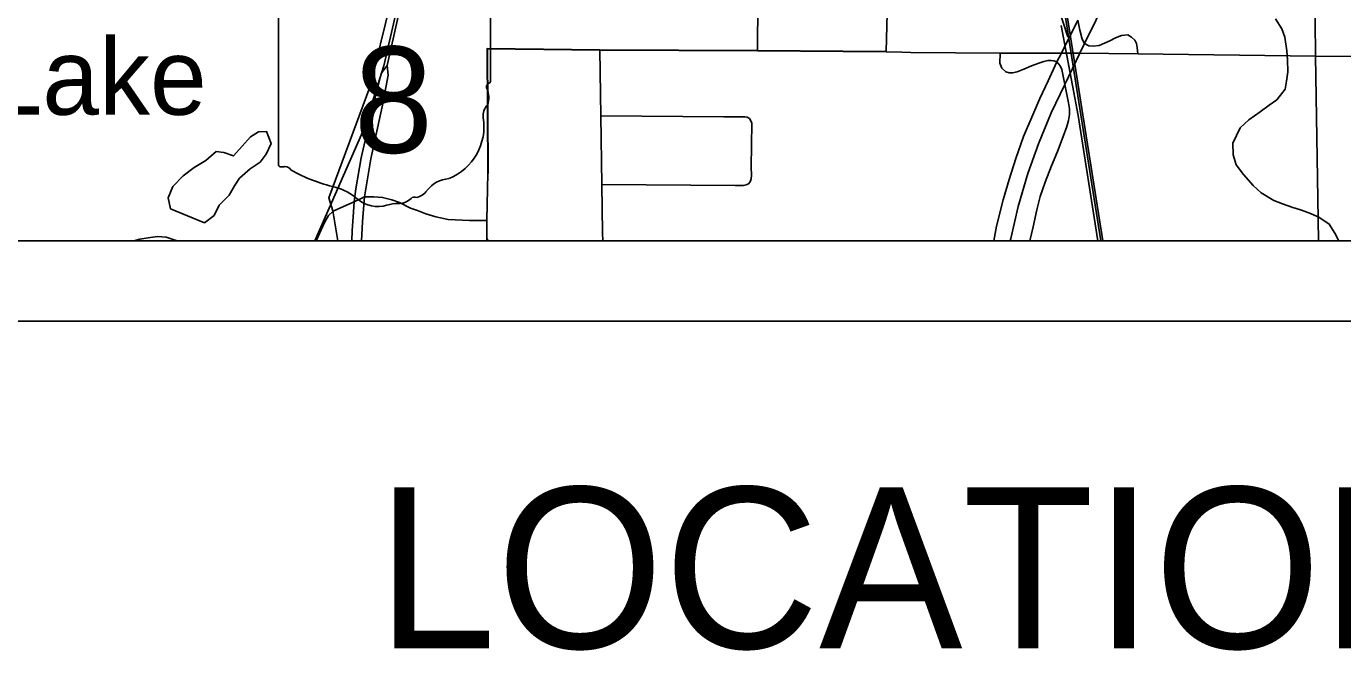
# Model space of a CAD drawing. Extents: x 0 to 34, y 0 to 22.
# Drawn here: x 3.992 to 5.628, y 13.591 to 14.366 of the extents above; entities that cross this region are included whole.
import ezdxf

# ---------------------------------------------------------------- set-up
doc = ezdxf.new("R2010")
doc.units = 0
for name, color, linetype in [('GM_X_City_Street', 7, 'Continuous'), ('GM_X_County_Road', 7, 'Continuous'), ('GM_X_County_Text', 7, 'Continuous'), ('GM_X_Interstate_Route', 7, 'Continuous'), ('GM_X_Minor_Lake', 7, 'Continuous'), ('GM_X_Minor_Lake_Text', 7, 'Continuous'), ('GM_X_Minor_River', 7, 'Continuous'), ('GM_X_Rail_Line', 7, 'Continuous'), ('GM_X_State_Location', 7, 'Continuous'), ('GM_X_State_Route', 7, 'Continuous'), ('GM_X_State_Shield', 7, 'Continuous'), ('SH_Cut_Line', 7, 'Continuous'), ('SH_Data', 7, 'Continuous'), ('SH_Text', 7, 'Continuous')]:
    doc.layers.add(name, color=color, linetype=linetype)

msp = doc.modelspace()

# ---------------------------------------------------------------- linework, layer by layer
at = {"layer": 'GM_X_City_Street'}
msp.add_line((4.5654, 14.1834), (4.5646, 14.3382), dxfattribs=at)
for points in [[(4.9002, 14.3359), (4.9007, 14.3967), (4.8987, 14.4155), (4.8935, 14.4274), (4.8863, 14.437), (4.8811, 14.4424), (4.8664, 14.4573), (4.86, 14.4669), (4.8572, 14.4785), (4.856, 14.4908), (4.856, 14.5164), (4.8569, 14.6404), (4.8589, 14.8045), (4.8604, 14.8098), (4.8626, 14.8139), (4.8658, 14.8174), (4.87, 14.8201), (4.8767, 14.8221), (4.9202, 14.8214), (4.9812, 14.821), (5.0417, 14.8203), (5.061, 14.821)], [(5.3729, 14.3321), (5.3721, 14.3402), (5.3714, 14.3449), (5.3694, 14.3492), (5.3653, 14.353), (5.3604, 14.3556), (5.3526, 14.355), (5.3454, 14.3522), (5.3384, 14.3484), (5.325, 14.3426), (5.3177, 14.3417), (5.3121, 14.3422), (5.3066, 14.3449), (5.3037, 14.3504), (5.3007, 14.3616), (5.2983, 14.3738)], [(4.5646, 14.3382), (4.7045, 14.3367), (4.9002, 14.3359), (5.0603, 14.3345), (5.0797, 14.3341), (5.0908, 14.334)], [(4.708, 14.1), (4.7078, 14.11), (4.707, 14.1699), (4.7057, 14.2552), (4.7045, 14.3367)], [(5.0908, 14.334), (5.2017, 14.3329), (5.2783, 14.3331), (5.3007, 14.333), (5.3729, 14.3321), (5.5939, 14.3294), (5.7667, 14.3284), (5.824, 14.3276), (6.0069, 14.3261), (6.1695, 14.3249), (6.2625, 14.3243), (6.5074, 14.3219), (6.6258, 14.3217)], [(5.2389, 14.1), (5.2427, 14.1175), (5.2475, 14.1385), (5.2516, 14.1548), (5.2579, 14.1727), (5.2657, 14.1929), (5.273, 14.2108), (5.2801, 14.2294), (5.2846, 14.2418), (5.2867, 14.2495), (5.2879, 14.2569), (5.2879, 14.2638), (5.2867, 14.2715), (5.2821, 14.2942), (5.2787, 14.3126), (5.2765, 14.3172), (5.2725, 14.3223), (5.2687, 14.3233), (5.2653, 14.3239), (5.2612, 14.3237), (5.2563, 14.3225), (5.25, 14.3206), (5.2408, 14.3174), (5.2312, 14.3131), (5.2229, 14.3098), (5.2174, 14.3084), (5.2129, 14.3086), (5.2089, 14.3098), (5.2038, 14.3142), (5.2014, 14.3204), (5.2017, 14.3329)], [(4.7057, 14.2552), (4.8586, 14.254), (4.8806, 14.254), (4.8845, 14.254), (4.8873, 14.2536), (4.8902, 14.252)], [(4.8891, 14.1707), (4.8912, 14.1731), (4.8924, 14.1768), (4.8928, 14.1815), (4.8926, 14.1913), (4.8932, 14.2461), (4.8922, 14.2491), (4.8902, 14.252)], [(4.707, 14.1699), (4.8726, 14.1686), (4.8828, 14.1686), (4.8863, 14.1693), (4.8891, 14.1707)], [(4.412, 14.1545), (4.4233, 14.1547), (4.4343, 14.1538), (4.4458, 14.1508), (4.4555, 14.1474), (4.4691, 14.1407), (4.4779, 14.1375), (4.488, 14.1335), (4.5007, 14.1296), (4.5158, 14.1263), (4.5422, 14.1253), (4.564, 14.125)], [(4.564, 14.125), (4.564, 14.1032), (4.5657, 14.1)]]:
    msp.add_lwpolyline(points, dxfattribs=at)
at = {"layer": 'GM_X_County_Road'}
for points in [[(5.5974, 14.1), (5.5966, 14.1523), (5.5939, 14.3294), (5.5929, 14.4174), (5.5923, 14.4494), (5.5901, 14.6081), (5.587, 14.7813), (5.5844, 14.9716), (5.5809, 15.1312), (5.5807, 15.2003), (5.5807, 15.2092), (5.5817, 15.2179), (5.5833, 15.2292), (5.5852, 15.2369), (5.5909, 15.2557), (5.5958, 15.2694), (5.6082, 15.3003), (5.6186, 15.3374)], [(4.3517, 14.1), (4.362, 14.1229), (4.3672, 14.1312), (4.3727, 14.1367), (4.3858, 14.1424), (4.3989, 14.1485), (4.412, 14.1545)]]:
    msp.add_lwpolyline(points, dxfattribs=at)
at = {"layer": 'GM_X_County_Text'}
for points in [[(2.1, 15.3556), (2.1, 14.1), (4.3787, 14.1), (4.3725, 14.1373), (4.3676, 14.1533), (4.4185, 14.2906), (4.4707, 14.5032), (4.0058, 14.5086), (4.0092, 14.8604), (4.002, 15.1777), (4.1154, 15.1803), (4.1171, 15.3509), (3.8077, 15.3535), (3.6529, 15.3542), (3.32, 15.3518), (3.0143, 15.3554), (2.8413, 15.3568), (2.5967, 15.3568)], [(4.5638, 14.1), (8.9, 14.1), (8.9, 15.3047), (6.6171, 15.3291), (6.0514, 15.3349), (5.911, 15.3352), (5.6184, 15.3359), (5.5738, 15.336), (5.5032, 15.3362), (5.4723, 15.3363), (5.4506, 15.3363), (5.4203, 15.3364), (5.0644, 15.3373), (5.0745, 14.9887), (5.0736, 14.8415), (5.0601, 14.3351), (4.9, 14.3365), (4.7043, 14.3373), (4.5643, 14.3387), (4.5652, 14.184), (4.5638, 14.1255), (4.5638, 14.1038)]]:
    msp.add_lwpolyline(points, close=True, dxfattribs=at)
msp.add_lwpolyline([(4.4707, 14.5032), (4.4185, 14.2906), (4.3676, 14.1533), (4.3725, 14.1373), (4.3787, 14.1), (4.5638, 14.1), (4.5638, 14.1038), (4.5638, 14.1255), (4.5652, 14.184), (4.5643, 14.3387), (4.7043, 14.3373), (4.9, 14.3365), (5.0601, 14.3351), (5.0736, 14.8415)], dxfattribs=at)
at = {"layer": 'GM_X_Interstate_Route'}
for points in [[(5.2145, 14.1), (5.215, 14.1027), (5.2243, 14.1427), (5.2364, 14.1836), (5.2495, 14.2205), (5.2653, 14.259), (5.2821, 14.2942), (5.3007, 14.333), (5.3066, 14.3449), (5.3353, 14.4032), (5.3682, 14.4712), (5.4005, 14.5369), (5.439, 14.6185), (5.4534, 14.6582), (5.4664, 14.6977), (5.4802, 14.7558), (5.4881, 14.8039), (5.4922, 14.8473), (5.4944, 14.8879), (5.4942, 14.9008)], [(5.1942, 14.1), (5.1975, 14.118), (5.2058, 14.151), (5.2131, 14.1762), (5.2215, 14.2023), (5.231, 14.2295), (5.2423, 14.2565), (5.2513, 14.2769), (5.2615, 14.2987), (5.2725, 14.3223), (5.2783, 14.3331), (5.2983, 14.3738)]]:
    msp.add_lwpolyline(points, dxfattribs=at)
at = {"layer": 'GM_X_Minor_Lake'}
for points in [[(4.2128, 14.1221), (4.2252, 14.1314), (4.2311, 14.1444), (4.2438, 14.1567), (4.2501, 14.1682), (4.2565, 14.1777), (4.2696, 14.1893), (4.282, 14.1978), (4.2895, 14.2077), (4.2958, 14.2207), (4.29, 14.2359), (4.2801, 14.2354), (4.2703, 14.2292), (4.2598, 14.2173), (4.249, 14.2054), (4.2372, 14.2098), (4.2273, 14.2108), (4.2145, 14.1997), (4.2002, 14.1908), (4.1863, 14.1807), (4.1736, 14.1673), (4.1677, 14.1535), (4.1709, 14.1395)], [(4.1709, 14.1395), (4.2128, 14.1221)]]:
    msp.add_lwpolyline(points, dxfattribs=at)
at = {"layer": 'GM_X_Minor_River'}
for points in [[(5.6227, 14.1), (5.6178, 14.1095), (5.6109, 14.1208), (5.598, 14.1294), (5.5854, 14.1346), (5.5751, 14.1383), (5.5656, 14.1413), (5.5527, 14.1457), (5.5421, 14.1502), (5.5264, 14.1595), (5.5165, 14.1685), (5.5042, 14.1825), (5.4954, 14.1942), (5.4915, 14.2067), (5.491, 14.2211), (5.5, 14.2402), (5.5109, 14.2502), (5.5252, 14.2602), (5.5361, 14.2683), (5.5459, 14.2752), (5.556, 14.2882), (5.5578, 14.2981), (5.5596, 14.3099), (5.5591, 14.3247), (5.5583, 14.3361), (5.5558, 14.3528), (5.552, 14.3634), (5.5443, 14.3755)], [(4.125, 14.1), (4.1326, 14.1019), (4.1428, 14.1035), (4.1546, 14.1051), (4.1652, 14.1045), (4.1777, 14.1005), (4.1782, 14.1)]]:
    msp.add_lwpolyline(points, dxfattribs=at)
at = {"layer": 'GM_X_Rail_Line'}
msp.add_line((5.2743, 14.3889), (5.2861, 14.3535), dxfattribs=at)
for points in [[(4.3502, 14.1), (4.411, 14.2385), (4.436, 14.3173), (4.5399, 14.7696), (4.6617, 15.3116), (4.6634, 15.349)], [(5.3272, 14.1), (5.3011, 14.2641), (5.1948, 14.9374), (5.138, 15.2939), (5.1305, 15.3389)], [(5.3296, 14.1), (5.3034, 14.2644), (5.1971, 14.9378), (5.1403, 15.2942), (5.1334, 15.338)], [(5.2778, 14.3673), (5.2988, 14.2557), (5.3233, 14.1)]]:
    msp.add_lwpolyline(points, dxfattribs=at)
at = {"layer": 'GM_X_State_Route'}
msp.add_line((4.4402, 14.3177), (4.4581, 14.3992), dxfattribs=at)
for points in [[(4.3962, 14.1), (4.3966, 14.1126), (4.3977, 14.1299), (4.3989, 14.1485), (4.4011, 14.1644), (4.4076, 14.2031), (4.4222, 14.2661), (4.4326, 14.3077), (4.4402, 14.3177)], [(4.4111, 14.1445), (4.412, 14.1545), (4.4199, 14.2016), (4.4341, 14.2685), (4.4414, 14.3055), (4.4402, 14.3177)], [(4.4082, 14.1), (4.4094, 14.1235), (4.4111, 14.1445)]]:
    msp.add_lwpolyline(points, dxfattribs=at)
at = {"layer": 'GM_X_State_Shield'}
for p, q in [((4.5686, 14.299), (4.5686, 14.4037)), ((4.3049, 14.3953), (4.3049, 14.1951)), ((4.5686, 14.299), (4.5686, 14.299))]:
    msp.add_line(p, q, dxfattribs=at)
for centre, radius, start, end in [((4.5655, 14.2986), 0.00314, 289.6038, 7.7341), ((4.5679, 14.2913), 0.00454, 107.944, 210.337), ((4.539, 14.2781), 0.0273, 340.033, 23.6496), ((4.5791, 14.2552), 0.0198, 136.8065, 186.9296), ((4.4904, 14.2419), 0.0699, 292.3089, 8.9858), ((4.308, 14.1947), 0.00308, 171.9584, 258.3066), ((4.3085, 14.2152), 0.0235, 267.339, 280.6039), ((4.3133, 14.1836), 0.00848, 29.7484, 93.2717), ((4.4203, 14.3634), 0.2019, 240.4129, 257.1985), ((4.5198, 14.139), 0.0383, 94.4031, 142.5768), ((4.3601, 14.1052), 0.0632, 47.1842, 75.836), ((4.4546, 14.1676), 0.0214, 268.777, 315.5493), ((4.4739, 14.1482), 0.00601, 65.7517, 132.6484), ((4.4713, 14.1757), 0.0226, 282.8732, 323.2771), ((4.4285, 14.1826), 0.0401, 230.7004, 286.2918), ((4.4516, 14.1134), 0.0329, 85.6951, 111.2099)]:
    msp.add_arc(centre, radius, start, end, dxfattribs=at)
at = {"layer": 'SH_Cut_Line'}
msp.add_lwpolyline([(2.1, 14.1), (8.9, 14.1)], dxfattribs=at)
at = {"layer": 'SH_Data'}
for p, q in [((2.1, 14.1), (8.9, 14.1)), ((2, 14), (9, 14))]:
    msp.add_line(p, q, dxfattribs=at)

# ---------------------------------------------------------------- texts
at = {"layer": 'GM_X_Minor_Lake_Text'}
msp.add_text('Lake', height=0.09475, rotation=359.9764, dxfattribs=at).set_placement((3.941, 14.2566))
at = {"layer": 'GM_X_State_Location'}
msp.add_text('8', height=0.000189, rotation=0, dxfattribs=at).set_placement((4.4053, 14.2681))
for s in ['s', 'r']:
    msp.add_text(s, height=0.000189, dxfattribs=at).set_placement((4.4338, 14.2819))
at = {"layer": 'GM_X_State_Shield'}
msp.add_text('8', height=0.1318, dxfattribs=at).set_placement((4.3988, 14.2093))
at = {"layer": 'SH_Text'}
msp.add_text('LOCATION MAP', height=0.2, dxfattribs=at).set_placement((4.4269, 13.5938))

doc.saveas('drawing.dxf')
